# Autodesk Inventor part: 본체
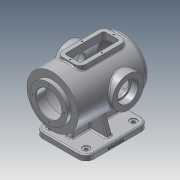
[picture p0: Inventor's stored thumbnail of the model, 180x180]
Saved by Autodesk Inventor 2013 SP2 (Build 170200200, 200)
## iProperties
Created: 2021-11
Part Number: 본체
Material: 알루미늄 6061
Document SubType Name: Modeling
Designer: i
Density: 2.71 g/cm^3
Mass: 3575.64 g
Surface Area: 2426.57 cm^2
Volume: 1319.43 cm^3
Author: i
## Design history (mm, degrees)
sketch "스케치2"
  geometry: L1 (-105, 0)-(105, 0); L2 (-105, 0)-(-105, 47.5); L3 (-105, 47.5)-(-95, 47.5); L4 (-95, 47.5)-(-95, 65); L5 (-95, 65)-(80.993, 65); L6 (80.993, 65)-(80.993, 0); A1 r 100 centre (5, 0) between (80.993, -65) and (80.993, 65); 2 further points
  constraints: 12 end point, 5 perpendicular, 3 point on circle, 1 centre point, 1 coincident, 1 horizontal, 1 midpoint, 1 point on line
  dimensions: "d29" = 210 distance of L1.end L1.start; "d30" = 10 distance between parallel lines of L4 L2; "d31" = 95 diameter of L3 L1; "d32" = 130 diameter of L5 L1; "d33" = 130 distance of L5.end A1.start; "d34" = 100 radius of A1
revolve "회전1" sketch "스케치2" stored, may be unused: angle "d35" = 90 deg
feature "쉘1" dims "d36" = 10
fillet "모깎기1" dims "d37" = 10
sketch "스케치3"
  geometry: L1 (-105, -37.5)-(-105, 37.5) reference; L2 (-85, 55)-(76.239, 55) reference; L3 (-95, -65)-(-95, 65) reference; L4 (76.239, -65)-(76.239, 65) reference; L5 (-85, -55)-(-85, 55) reference; L6 (-105, 37.5)-(-85, 37.5) reference; L7 (-105, 0)-(-80, 0); L8 (-80, 0)-(-80, 55); A1 r 90 centre (5, 0) between (76.239, -55) and (76.239, 55) reference; 1 further point
  constraints: 4 end point, 1 midpoint, 1 parallel, 1 perpendicular, 1 point on line
  dimensions: "d38" = 25 distance of L7.start L7.end
revolve "회전2" sketch "스케치3" stored, may be unused: angle "d39" = 90 deg
sketch "스케치4"
  geometry: C1 r 47.5 at (0, 0) reference; 1 further point
  constraints: 1 coincident
hole "구멍1" sketch "스케치4" at (0, 0) diameter "d40" = 65; stored, may be unused: countersink angle "d44" = 90 deg, drill point angle "d46" = 118 deg; dims "d41" = 6, "d42" = 4, "d43" = 2, "d45" = 30
fillet "모깎기2" dims "d47" = 3
node "작업 평면1"
sketch "스케치5"
  geometry: L1 (95, -65)-(-76.239, -65) reference; L2 (95, 65)-(95, -65) reference; L3 (105, -47.5)-(95, -47.5) reference; L4 (105, 47.5)-(105, -47.5) reference; L5 (40, -30)-(-50, -30); L6 (-65, -15)-(-65, 15); L7 (-50, 30)-(40, 30); L8 (55, 15)-(55, -15); A1 r 100 centre (-5, 0) between (-84.154, 61.111) and (-84.154, -61.111) reference; A2 r 10 centre (-76.239, -55) between (-84.154, -61.111) and (-76.239, -65) reference; A3 r 15 centre (40, -15) between (40, -30) and (55, -15); A4 r 15 centre (40, 15) between (55, 15) and (40, 30); A5 r 15 centre (-50, 15) between (-50, 30) and (-65, 15); A6 r 15 centre (-50, -15) between (-65, -15) and (-50, -30); 5 further points
  constraints: 8 end point, 8 point on circle, 8 tangent, 6 point on line, 4 centre point, 3 equal radius, 2 midpoint, 2 parallel, 1 horizontal, 1 horizontal alignment, 1 perpendicular
  dimensions: "d49" = 120 distance of point (-65, 30) point (55, 30); "d50" = 60 distance of point (-65, -30) point (-65, 30); "d51" = 50 distance between parallel lines of L4 L8; "d52" = 15 radius of A3
extrude "돌출1" join sketch "스케치5" stored distance "d54" = 10; taper "d55" = 0 deg
sketch "스케치6"
  geometry: L1 (-40, 30)-(50, 30) reference; L2 (-55, -15)-(-55, 15) reference; L3 (50, -30)-(-40, -30) reference; L4 (65, 15)-(65, -15) reference; L5 (50, 20)-(-40, 20); L6 (-45, 15)-(-45, -15); L7 (-40, -20)-(50, -20); L8 (55, -15)-(55, 15); A1 r 15 centre (-40, 15) between (-40, 30) and (-55, 15) reference; A2 r 15 centre (-40, -15) between (-55, -15) and (-40, -30) reference; A3 r 15 centre (50, -15) between (50, -30) and (65, -15) reference; A4 r 15 centre (50, 15) between (65, 15) and (50, 30) reference; A5 r 5 centre (-40, 15) between (-40, 20) and (-45, 15); A6 r 5 centre (-40, -15) between (-45, -15) and (-40, -20); A7 r 5 centre (50, -15) between (50, -20) and (55, -15); A8 r 5 centre (50, 15) between (55, 15) and (50, 20); 1 further point
  constraints: 8 end point, 8 point on circle, 4 centre point, 7 other
  dimensions: "d56" = 10 distance between parallel lines of L5 L1
extrude "돌출2" cut sketch "스케치6" stored distance "d57" = 10; taper "d58" = 0 deg
node "작업 평면2"
sketch "스케치8"
  geometry: L1 (-105, -47.5)-(-105, 47.5) reference; L2 (-105, 0)-(22, 0); C1 r 40 at (22, 0); 1 further point
  constraints: 2 end point, 1 centre point, 1 coincident, 1 midpoint, 1 perpendicular
  dimensions: "d60" = 127 distance of L2.start L2.end; "d61" = 80 diameter of C1
extrude "돌출3" join sketch "스케치8" stored distance "d62" = 10; taper "d63" = 0 deg
sketch "스케치9"
  geometry: C1 r 40 at (0, 0) reference; C2 r 26 at (0, 0); 1 further point
  constraints: 1 centre point, 1 coincident
  dimensions: "d64" = 52 diameter of C2
extrude "돌출4" cut sketch "스케치9" distance "d65" = 18; taper "d66" = 0 deg
sketch "스케치10"
  geometry: C1 r 26 at (0, 0) reference; C2 r 21 at (0, 0); 1 further point
  constraints: 1 centre point, 1 coincident
  dimensions: "d67" = 42 diameter of C2
extrude "돌출5" cut sketch "스케치10" stored distance "d68" = 18; taper "d69" = 0 deg
fillet "모깎기3" dims "d70" = 0.3
chamfer "모따기1" distance "d71" = 1; stored, may be unused: second distance "d72" = 2, angle "d73" = 45 deg
sketch "스케치11"
  geometry: L1 (0, 0)-(0, 32.5); C1 r 27 at (0, 0) reference; 2 further points
  constraints: 2 end point, 1 coincident, 1 vertical
  dimensions: "d74" = 32.5 distance of L1.start L1.end
hole "구멍2" sketch "스케치11" at (0, 32.5) diameter "d75" = 3.242; stored, may be unused: countersink angle "d79" = 90 deg, drill point angle "d81" = 118 deg; dims "d76" = 11, "d77" = 52, "d78" = 18, "d80" = 13
sketch "스케치12"
  geometry: L1 (-40, 30)-(50, 30) reference; L2 (-55, -15)-(-55, 15) reference; L3 (50, -30)-(-40, -30) reference; L4 (65, 15)-(65, -15) reference; L5 (-55, 0)-(-50, 0); L6 (65, 0)-(60, 0); L7 (5, 30)-(5, 25); L8 (5, -30)-(5, -25); 5 further points
  constraints: 8 end point, 4 coincident, 4 midpoint, 2 collinear, 2 perpendicular
  dimensions: "d85" = 5 distance of L5.start L5.end; "d86" = 5 distance of L6.start L6.end; "d87" = 5 distance of L7.start L7.end; "d88" = 5 distance of L8.start L8.end
hole "구멍3" sketch "스케치12" at (5, 25), (-50, 0), (5, -25), (60, 0) diameter "d89" = 3.242; stored, may be unused: countersink angle "d93" = 90 deg, drill point angle "d95" = 118 deg; dims "d90" = 9, "d91" = 52, "d92" = 18, "d94" = 11
sketch "스케치13"
  geometry: L1 (0, 0)-(0, 40); C1 r 47.5 at (0, 0) reference; 1 further point
  constraints: 2 end point, 1 coincident, 1 vertical
  dimensions: "d96" = 40 distance of L1.start L1.end
hole "구멍4" sketch "스케치13" at (0, 40) diameter "d97" = 3.242; stored, may be unused: countersink angle "d101" = 90 deg, drill point angle "d103" = 118 deg; dims "d98" = 11, "d99" = 52, "d100" = 18, "d102" = 13
node "작업 평면3"
sketch "스케치14"
  geometry: L1 (105, 47.5)-(105, -47.5) reference; L2 (75, 65)-(-85, 65); L3 (-85, 65)-(-85, -65); L4 (-85, -65)-(75, -65); L5 (75, -65)-(75, 65); L6 (75, 65)-(-85, -65); L7 (-85, 65)-(75, -65); 3 further points
  constraints: 12 end point, 3 midpoint, 2 parallel, 1 horizontal, 1 horizontal alignment, 1 perpendicular
  dimensions: "d108" = 160 distance of L4.end L3.end; "d109" = 130 distance of L3.end L2.end; "d110" = 30 distance between parallel lines of L1 L5
extrude "돌출6" join sketch "스케치14" distance "d111" = 14; taper "d112" = 0 deg
fillet "모깎기4" dims "d113" = 20
sketch "스케치15"
  geometry: A1 r 20 centre (-55, -45) between (-75, -45) and (-55, -65) reference; A2 r 20 centre (65, -45) between (65, -65) and (85, -45) reference; A3 r 20 centre (65, 45) between (85, 45) and (65, 65) reference; A4 r 20 centre (-55, 45) between (-55, 65) and (-75, 45) reference; 5 further points
  constraints: 4 coincident
hole "구멍5" sketch "스케치15" at (-55, 45), (65, 45), (65, -45), (-55, -45) diameter "d114" = 9; stored, may be unused: countersink angle "d118" = 90 deg, drill point angle "d120" = 118 deg; dims "d115" = 11, "d116" = 18, "d117" = 2, "d119" = 14
sketch "스케치21"
  geometry: L1 (85, -45)-(85, 45) reference; L2 (65, 65)-(-55, 65) reference; L3 (-55, -7)-(65, -7); L4 (65, -7)-(65, 7); L5 (65, 7)-(-55, 7); L6 (-55, 7)-(-55, -7); L7 (-55, -7)-(65, 7); L8 (65, -7)-(-55, 7); 2 further points
  constraints: 12 end point, 2 midpoint, 2 parallel, 1 horizontal, 1 perpendicular
  dimensions: "d143" = 120 distance of L5.end L4.end; "d144" = 14 distance of L4.end L3.end; "d145" = 80 distance from line of L1 point (5, 0); "d146" = 65 distance from line of L2 point (5, 0)
extrude "돌출8" join sketch "스케치21" stored distance "d147" = 14; taper "d148" = 0 deg
feature "면 기울기1" dims angle "d149" = 20 deg
feature "면 기울기2" dims angle "d150" = 20 deg
sketch "스케치23"
  geometry: L1 (-13.856, 74)-(-13.856, 57.3) reference; L2 (-13.285, 57)-(13.285, 57) reference; L3 (13.856, 57.3)-(13.856, 74) reference; L4 (15.652, 75)-(33.407, 75) reference; L5 (33.407, 75)-(33.407, 55.758) reference; L6 (57.663, 30)-(70, 30) reference; L7 (70, 30)-(70, 20) reference; L8 (70, 20)-(51.235, 20) reference; L9 (51.235, -20)-(70, -20) reference; L10 (70, -20)-(70, -30) reference; L11 (70, -30)-(57.663, -30) reference; L12 (33.407, -55.758)-(33.407, -75) reference; L13 (33.407, -75)-(15.652, -75) reference; L14 (13.856, -74)-(13.856, -57.3) reference; L15 (13.285, -57)-(-13.285, -57) reference; L16 (-13.856, -57.3)-(-13.856, -74) reference; L17 (-15.652, -75)-(-33.407, -75) reference; L18 (-33.407, -75)-(-33.407, -55.758) reference; L19 (-64.622, -7)-(-100, -7) reference; L20 (-100, -7)-(-100, -65) reference; L21 (-100, -65)-(-114, -65) reference; L22 (-114, -65)-(-114, 65) reference; L23 (-114, 65)-(-100, 65) reference; L24 (-100, 65)-(-100, 7) reference; L25 (-100, 7)-(-64.622, 7) reference; L26 (-33.407, 55.758)-(-33.407, 75) reference; L27 (-33.407, 75)-(-15.652, 75) reference; L28 (-55.515, 33.809)-(-100, 50); A1 r 65 centre (0, 0) between (57.663, 30) and (33.407, 55.758) reference; A2 r 55 centre (0, 0) between (51.235, 20) and (51.235, -20) reference; A3 r 65 centre (0, 0) between (33.407, -55.758) and (57.663, -30) reference; A4 r 65 centre (0, 0) between (-64.622, -7) and (-33.407, -55.758) reference; A5 r 65 centre (0, 0) between (-33.407, 55.758) and (-64.622, 7) reference; 1 further point
  constraints: 2 end point, 1 point on circle, 1 point on line, 8 other
  dimensions: "d151" = 110 deg angle of L24 L28; "d153" = 50 vertical distance of L28.end point (0, 0)
feature "리브2" sketch "스케치23" dims "d154" = 1, "d155" = 14, "d156" = 0, "d157" = 0, "d158" = 1, "d159" = 1
fillet "모깎기7" dims "d160" = 3
fillet "모깎기8" dims "d161" = 3
fillet "모깎기9" dims "d162" = 3
chamfer "모따기2" distance "d163" = 1; stored, may be unused: second distance "d164" = 2, angle "d165" = 45 deg
sketch "스케치24"
  geometry: L1 (0, 0)-(120, 0) reference; L2 (51, 14)-(59, 14) reference; 3 further points
  constraints: 1 midpoint, 1 vertical alignment, 1 other
  dimensions: "d166" = 5 distance from line of L1 point (55, 5)
feature "엠보싱1" sketch "스케치24" dims "d167" = 0.5, "d168" = 0
node "솔리드1"
mirror "대칭1"
pattern_circular "원형 패턴1" dims angle "d83" = 360 deg
mirror "대칭2"
pattern_circular "원형 패턴2" dims angle "d105" = 360 deg
mirror "대칭4"
node "투영된 루프1"
node "절단 모서리 투영5"
other parameters: "d59" = 75, "d107" = -114
